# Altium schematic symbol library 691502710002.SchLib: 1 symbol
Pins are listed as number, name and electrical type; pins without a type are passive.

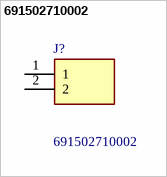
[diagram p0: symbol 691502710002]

## 691502710002
designator J?
2 Position Wire to Board Terminal Block Horizontal with Board 0.197" (5.00mm) Through Hole; Manufacturer_Name: Wurth Elektronik; Geometry.Height: 10.3mm
footprint 691502710002
pins: 1, 2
